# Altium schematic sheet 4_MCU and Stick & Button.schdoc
size 370 x 241 mm
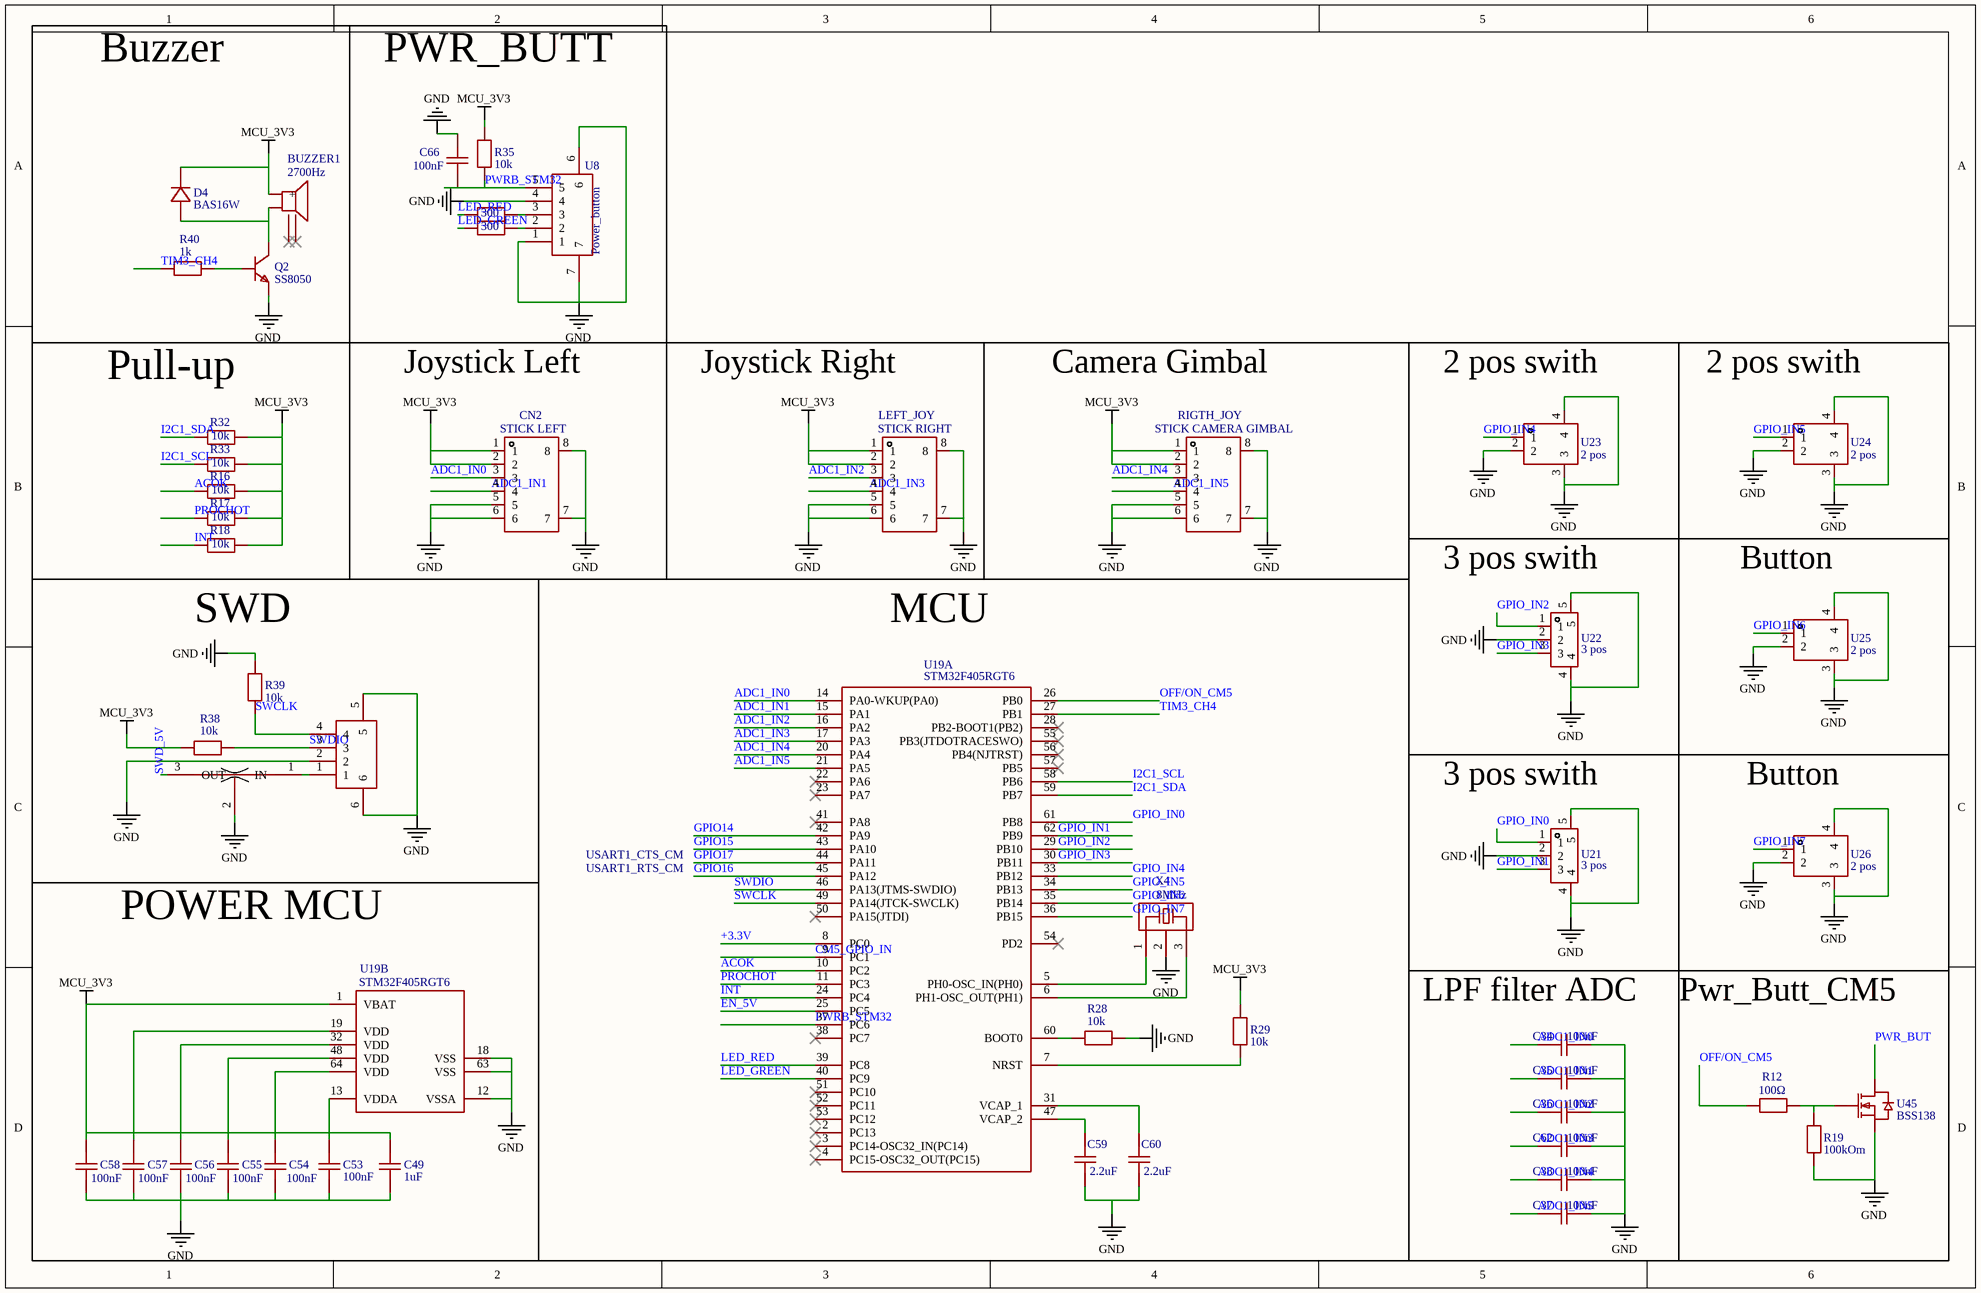
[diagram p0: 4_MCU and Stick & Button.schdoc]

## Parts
BUZZER1  2700Hz  [BUZ-SMD_4P-L8.5-W8.5-P8.50-BR]
C34  100nF  [C0603]
C35  100nF  [C0603]
C36  100nF  [C0603]
C37  100nF  [C0603]
C38  100nF  [C0603]
C49  1uF  [C0603]
C53  100nF  [C0603]
C54  100nF  [C0603]
C55  100nF  [C0603]
C56  100nF  [C0603]
C57  100nF  [C0603]
C58  100nF  [C0603]
C59  2.2uF  [C0603]
C60  2.2uF  [C0603]
C61  -  [FILTER-SMD_3P-L1.6-W0.8-L_NFM18CC223R1C3D]  (value not drawn)
C62  100nF  [C0603]
C66  100nF  [C0603]
CN2  STICK LEFT  [CONN-TH_SM06B-GHS-TB-LF-SN]
D4  BAS16W  [SOD-123_L2.7-W1.6-LS3.7-RD]
LEFT_JOY  STICK RIGHT  [CONN-TH_SM06B-GHS-TB-LF-SN]
Q2  SS8050  [SOT-23-3_L2.9-W1.3-P1.90-LS2.4-BR]
R12  100Ω  [R0402]
R16  10k  [R0603]
R17  10k  [R0603]
R18  10k  [R0603]
R19  100kOm  [R0402]
R20  300  [R0603]
R28  10k  [R0603]
R29  10k  [R0603]
R32  10k  [R0603]
R33  10k  [R0603]
R34  300  [R0603]
R35  10k  [R0603]
R38  10k  [R0603]
R39  10k  [R0603]
R40  1k  [R0603]
RIGTH_JOY  STICK CAMERA GIMBAL  [CONN-TH_SM06B-GHS-TB-LF-SN]
U8  Power_button  [CONN-SMD_5P-P1.25_SM05B-GHS-TB-LF-SN]
U19  STM32F405RGT6  [LQFP-64_L10.0-W10.0-P0.50-LS12.0-BL]  (parts A,B of 2)
U21  3 pos  [CONN-TH_SM03B-GHS-TB-LF-SN]
U22  3 pos  [CONN-TH_SM03B-GHS-TB-LF-SN]
U23  2 pos  [CONN-SMD_SM02B-GHS-TB-LF-SN]
U24  2 pos  [CONN-SMD_SM02B-GHS-TB-LF-SN]
U25  2 pos  [CONN-SMD_SM02B-GHS-TB-LF-SN]
U26  2 pos  [CONN-SMD_SM02B-GHS-TB-LF-SN]
U30  SM04B-GHS-TB(LF)(SN)  [CONN-SMD_4P-P1.25_SM04B-GHS-TB-LF-SN]  (value not drawn)
U45  BSS138  [SOT-23-3_L2.9-W1.4-P1.90-LS2.5-BR]
X4  8MHz  [OSC-SMD_3P-L3.2-W1.3-P1.2-L]

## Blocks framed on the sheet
Buzzer: BUZZER1 D4 Q2 R40
PWR_BUTT: C66 R20 R34 R35 U8
Pull-up: R16-R18 R32 R33
Joystick Left: CN2
Joystick Right: LEFT_JOY
Camera Gimbal: RIGTH_JOY
2 pos swith: U23
2 pos swith: U24
3 pos swith: U22
Button: U25
SWD: C61 R38 R39 U30
MCU: C59 C60 R28 R29 U19 X4
3 pos swith: U21
Button: U26
POWER MCU: C49 C53-C58 U19
LPF filter ADC: C34-C38 C62
Pwr_Butt_CM5: R12 R19 U45

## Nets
GND: C34.2 C35.2 C36.2 C37.2 C38.2 C49.1 C53.1 C54.1 C55.1 C56.1 C57.1 C58.1 C59.1 C60.1 C61.2(GND) C62.2 C66.2 CN2.5 CN2.6 CN2.7 CN2.8 LEFT_JOY.5 LEFT_JOY.6 LEFT_JOY.7 LEFT_JOY.8 Q2.2(E) R19.1 R28.1 R39.2 RIGTH_JOY.5 RIGTH_JOY.6 RIGTH_JOY.7 RIGTH_JOY.8 U8.1 U8.4 U8.6 U8.7 U19.12(VSSA) U19.18(VSS) U19.63(VSS) U21.2 U21.4 U21.5 U22.2 U22.4 U22.5 U23.2 U23.3 U23.4 U24.2 U24.3 U24.4 U25.2 U25.3 U25.4 U26.2 U26.3 U26.4 U30.2 U30.5 U30.6 U45.2(S) X4.2
MCU_3V3: BUZZER1.1(+) C49.2 C53.2 C54.2 C55.2 C56.2 C57.2 C58.2 CN2.1 CN2.2 D4.1(K) LEFT_JOY.1 LEFT_JOY.2 R16.2 R17.2 R18.2 R29.1 R32.2 R33.2 R35.2 R38.1 RIGTH_JOY.1 RIGTH_JOY.2 U19.1(VBAT) U19.13(VDDA) U19.19(VDD) U19.32(VDD) U19.48(VDD) U19.64(VDD)
+3.3V: U19.8(PC0)
ACOK: R16.1 U19.10(PC2)
ADC1_IN0: C34.1 CN2.3 U19.14(PA0-WKUP(PA0))
ADC1_IN1: C35.1 CN2.4 U19.15(PA1)
ADC1_IN2: C36.1 LEFT_JOY.3 U19.16(PA2)
ADC1_IN3: C62.1 LEFT_JOY.4 U19.17(PA3)
ADC1_IN4: C38.1 RIGTH_JOY.3 U19.20(PA4)
ADC1_IN5: C37.1 RIGTH_JOY.4 U19.21(PA5)
CM5_GPIO_IN: U19.9(PC1)
EN_5V: U19.25(PC5)
GPIO14: U19.42(PA9)
GPIO15: U19.43(PA10)
GPIO16: U19.45(PA12)
GPIO17: U19.44(PA11)
GPIO_IN0: U19.61(PB8) U21.1
GPIO_IN1: U19.62(PB9) U21.3
GPIO_IN2: U19.29(PB10) U22.1
GPIO_IN3: U19.30(PB11) U22.3
GPIO_IN4: U19.33(PB12) U23.1
GPIO_IN5: U19.34(PB13) U24.1
GPIO_IN6: U19.35(PB14) U25.1
GPIO_IN7: U19.36(PB15) U26.1
I2C1_SCL: R33.1 U19.58(PB6)
I2C1_SDA: R32.1 U19.59(PB7)
INT: R18.1 U19.24(PC4)
LED_GREEN: R34.1 U19.40(PC9)
LED_RED: R20.1 U19.39(PC8)
OFF/ON_CM5: R12.1 U19.26(PB0)
PROCHOT: R17.1 U19.11(PC3)
PWR_BUT: U45.3(D)
PWRB_STM32: C66.1 R35.1 U8.5 U19.37(PC6)
SWCLK: R39.1 U19.49(PA14(JTCK-SWCLK)) U30.4
SWD_5V: C61.3(OUT)
SWDIO: R38.2 U19.46(PA13(JTMS-SWDIO)) U30.3
TIM3_CH4: R40.1 U19.27(PB1)
NetBUZZER1_2: BUZZER1.2 D4.2(A) Q2.3(C)
NetC59_2: C59.2 U19.47(VCAP_2)
NetC60_2: C60.2 U19.31(VCAP_1)
NetC61_1: C61.1(IN) U30.1
NetQ2_1: Q2.1(B) R40.2
NetR12_2: R12.2 R19.2 U45.1(G)
NetR20_2: R20.2 U8.3
NetR28_2: R28.2 U19.60(BOOT0)
NetR29_2: R29.2 U19.7(NRST)
NetR34_2: R34.2 U8.2
NetU19_5: U19.5(PH0-OSC_IN(PH0)) X4.1
NetU19_6: U19.6(PH1-OSC_OUT(PH1)) X4.3

Not connected (* = marked no-connect by the designer): BUZZER1 3* 4*; U19 2(PC13)* 3(PC14-OSC32_IN(PC14))* 4(PC15-OSC32_OUT(PC15))* 22(PA6)* 23(PA7)* 28(PB2-BOOT1(PB2))* 38(PC7)* 41(PA8)* 50(PA15(JTDI))* 51(PC10)* 52(PC11)* 53(PC12)* 54(PD2)* 55(PB3(JTDOTRACESWO))* 56(PB4(NJTRST))* 57(PB5)*

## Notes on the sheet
- USART1_RTS_CM
- USART1_CTS_CM

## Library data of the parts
BUZZER1 = 2700Hz: Manufacturer: 华能; Convert to PCB: yes; nameAlias: Value
C34-C38 C53-C58 C62 C66 = 100nF: Convert to PCB: yes; nameAlias: Value(F); Contributor: LCEDA_Lib
C49 = 1uF: Convert to PCB: yes; nameAlias: Value(F); Contributor: LCEDA_Lib
C59 C60 = 2.2uF: Convert to PCB: yes; nameAlias: Value(F); Contributor: LCEDA_Lib
C61 = -: Manufacturer: muRata(村田); Manufacturer Part: NFM18PC104R1C3D; Convert to PCB: yes; nameAlias: Value
CN2 = STICK LEFT: Manufacturer: JST; Manufacturer Part: SM06B-GHS-TB(LF)(SN); Convert to PCB: yes; Contributor: LCSC
D4 = BAS16W: Manufacturer: YANGJIE(扬杰); Convert to PCB: yes; Contributor: LCSC
LEFT_JOY = STICK RIGHT: Manufacturer: JST; Manufacturer Part: SM06B-GHS-TB(LF)(SN); Convert to PCB: yes; Contributor: LCSC
Q2 = SS8050: Manufacturer: FUXINSEMI(富芯森美); Convert to PCB: yes; Contributor: LCSC
R12 = 100Ω: Convert to PCB: yes; nameAlias: Value(Ω); Contributor: LCEDA_Lib
R16-R18 R28 R29 R32 R33 R35 R38 R39 = 10k: Convert to PCB: yes; nameAlias: Value(Ω); Contributor: LCEDA_Lib
R19 = 100kOm: Convert to PCB: yes; nameAlias: Value(Ω); Contributor: LCEDA_Lib
R20 R34 = 300: Convert to PCB: yes; nameAlias: Value(Ω); Contributor: LCEDA_Lib
R40 = 1k: Convert to PCB: yes; nameAlias: Value(Ω); Contributor: LCEDA_Lib
RIGTH_JOY = STICK CAMERA GIMBAL: Manufacturer: JST; Manufacturer Part: SM06B-GHS-TB(LF)(SN); Convert to PCB: yes; Contributor: LCSC
U8 = Power_button: Manufacturer: JST; Manufacturer Part: SM05B-GHS-TB(LF)(SN); Convert to PCB: yes; Contributor: LCSC
U19 = STM32F405RGT6: Manufacturer: ST(意法半导体); subpart_no: 1; tags: STM32; Convert to PCB: yes
U21 U22 = 3 pos: Manufacturer: JST; Manufacturer Part: SM03B-GHS-TB(LF)(SN); Convert to PCB: yes; Contributor: LCSC
U23-U26 = 2 pos: Manufacturer: JST; Manufacturer Part: SM02B-GHS-TB(LF)(SN); Convert to PCB: yes; Contributor: LCSC
U30 = SM04B-GHS-TB(LF)(SN): Manufacturer: JST; Convert to PCB: yes; Contributor: LCSC
U45 = BSS138: Manufacturer: Zhengxin(正芯); Convert to PCB: yes; Contributor: lcsc
X4 = 8MHz: Manufacturer Part: CSTCE8M00G52-R0; Manufacturer: muRata(村田); Convert to PCB: yes; nameAlias: Value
